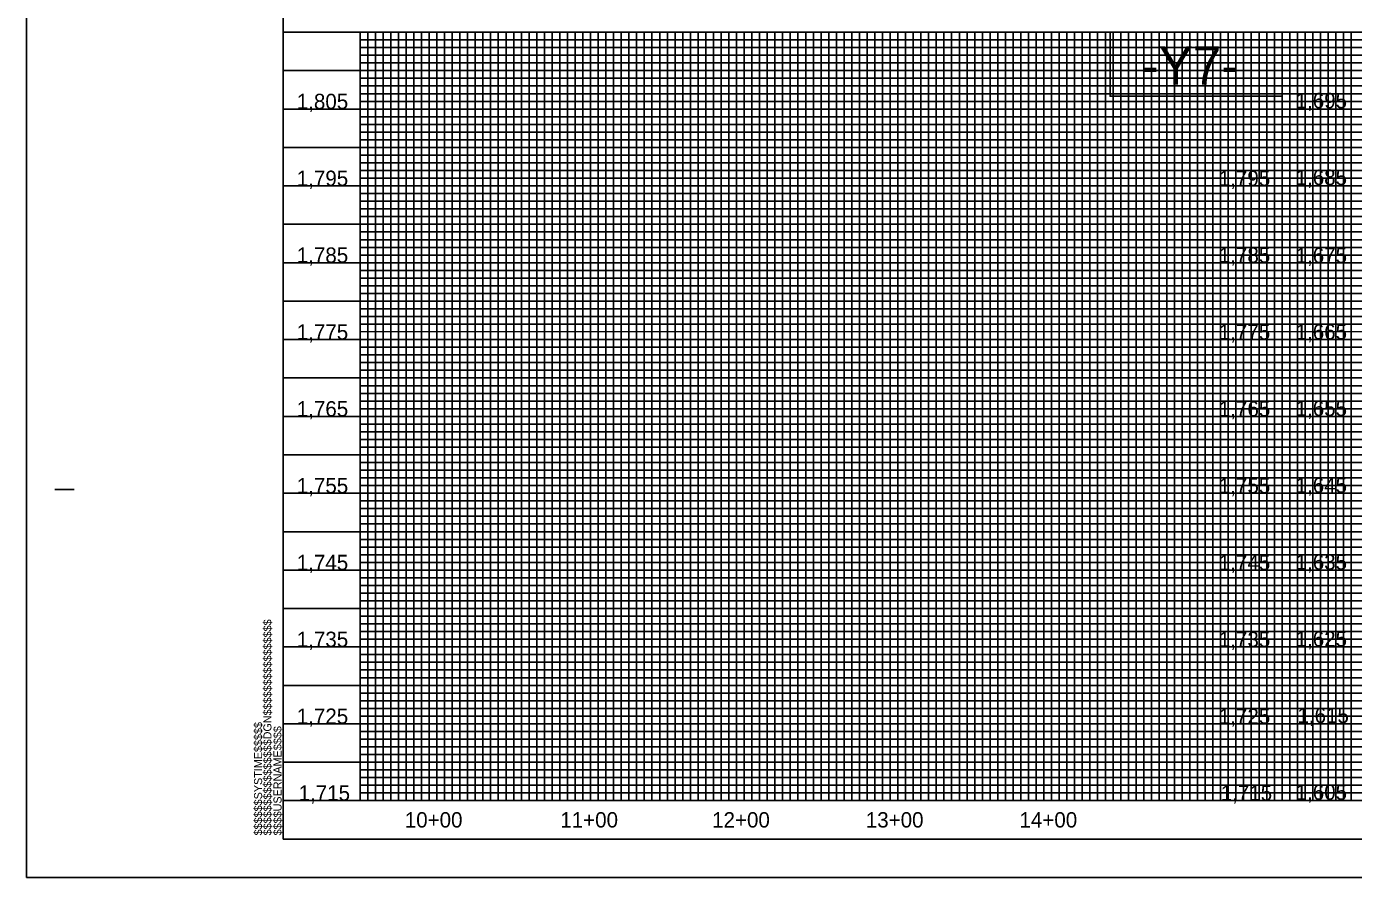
# Model space of a CAD drawing. Extents: x 505602 to 507286, y 483109 to 489436.
# Drawn here: x 505602 to 506466, y 483109 to 483662 of the extents above; entities that cross this region are included whole.
import ezdxf

# ---------------------------------------------------------------- set-up
doc = ezdxf.new("R2010")
doc.units = 0
for name, color, linetype in [('Exist Vertical Profile Vertical Axis Label', 7, 'Continuous'), ('Old_Level_1', 7, 'Continuous'), ('Prop Grid Mask', 7, 'Continuous'), ('Sheet Layout Profile Border Port 2', 7, 'Continuous'), ('Sheet Plot Border Outside CELL', 7, 'Continuous'), ('Sheet Profile CELL', 7, 'Continuous'), ('Sheet Profile Grid Major CELL', 7, 'Continuous'), ('Sheet Profile Grid Middle CELL', 7, 'Continuous'), ('Sheet Profile Grid Minor CELL', 7, 'Continuous')]:
    doc.layers.add(name, color=color, linetype=linetype)

msp = doc.modelspace()

# ---------------------------------------------------------------- linework, layer by layer
at = {"layer": 'Prop Grid Mask'}
msp.add_lwpolyline([(506419.08, 483658.71), (506307.17, 483658.71), (506307.17, 483617), (506419.08, 483617)], close=True, dxfattribs=at)
at = {"layer": 'Sheet Layout Profile Border Port 2'}
msp.add_lwpolyline([(505819.08, 483658.71), (506419.08, 483658.71), (506419.08, 483158.71), (505819.08, 483158.71)], close=True, dxfattribs=at)
at = {"layer": 'Sheet Plot Border Outside CELL'}
msp.add_lwpolyline([(505602.08, 483108.71), (507286.08, 483108.71), (507286.08, 484208.71), (505602.08, 484208.71)], close=True, dxfattribs=at)
at = {"layer": 'Sheet Profile CELL'}
for p, q in [((505769.08, 483658.71), (507269.08, 483658.71)), ((506419.08, 483158.71), (506419.08, 483658.71)), ((505620.58, 483361.21), (505633.08, 483361.21)), ((507269.08, 483158.71), (505769.08, 483158.71)), ((505769.08, 483133.71), (507269.08, 483133.71)), ((505769.08, 483133.71), (505769.08, 483133.71)), ((505769.08, 483133.71), (505769.08, 483133.71)), ((505769.08, 483133.71), (505769.08, 483133.71)), ((505769.08, 483133.71), (505769.08, 483133.71)), ((505769.08, 483133.71), (505769.08, 483133.71)), ((505769.08, 483133.71), (505769.08, 483133.71)), ((505769.08, 483133.71), (505769.08, 483133.71))]:
    msp.add_line(p, q, dxfattribs=at)
msp.add_lwpolyline([(507269.08, 484183.71), (505769.08, 484183.71), (505769.08, 483133.71), (507269.08, 483133.71)], close=True, dxfattribs=at)
msp.add_lwpolyline([(505806.58, 483133.71), (505806.58, 483133.71)], dxfattribs=at)
at = {"layer": 'Sheet Profile Grid Major CELL'}
for p, q in [((506269.08, 483658.71), (506319.08, 483658.71)), ((506369.08, 483658.71), (506419.08, 483658.71))]:
    msp.add_line(p, q, dxfattribs=at)
for points in [[(505819.08, 483658.71), (505819.08, 483158.71), (505869.08, 483158.71), (505869.08, 483658.71), (505919.08, 483658.71), (505919.08, 483158.71), (505969.08, 483158.71), (505969.08, 483658.71), (506019.08, 483658.71), (506019.08, 483158.71), (506069.08, 483158.71), (506069.08, 483658.71), (506119.08, 483658.71), (506119.08, 483158.71), (506169.08, 483158.71), (506169.08, 483658.71), (506219.08, 483658.71), (506219.08, 483158.71), (506269.08, 483158.71), (506269.08, 483658.71), (506319.08, 483658.71), (506319.08, 483158.71), (506369.08, 483158.71), (506369.08, 483658.71), (506419.08, 483658.71), (506419.08, 483158.71), (506469.08, 483158.71)], [(505819.08, 483658.71), (505819.08, 483158.71), (505869.08, 483158.71), (505869.08, 483658.71), (505919.08, 483658.71), (505919.08, 483158.71), (505969.08, 483158.71), (505969.08, 483658.71), (506019.08, 483658.71), (506019.08, 483158.71), (506069.08, 483158.71), (506069.08, 483658.71), (506119.08, 483658.71), (506119.08, 483158.71), (506169.08, 483158.71), (506169.08, 483658.71), (506219.08, 483658.71), (506219.08, 483158.71), (506269.08, 483158.71), (506269.08, 483658.71), (506319.08, 483658.71), (506319.08, 483158.71), (506369.08, 483158.71), (506369.08, 483658.71), (506419.08, 483658.71), (506419.08, 483158.71), (506469.08, 483158.71)], [(507269.08, 483608.71), (505769.08, 483608.71)], [(507269.08, 483558.71), (505769.08, 483558.71), (505769.08, 483508.71), (507269.08, 483508.71)], [(507269.08, 483458.71), (505769.08, 483458.71), (505769.08, 483408.71), (507269.08, 483408.71)], [(507269.08, 483358.71), (505769.08, 483358.71), (505769.08, 483308.71), (507269.08, 483308.71)], [(507269.08, 483258.71), (505769.08, 483258.71), (505769.08, 483258.71), (505769.08, 483208.71), (507269.08, 483208.71)], [(507269.08, 483158.71), (505769.08, 483158.71)]]:
    msp.add_lwpolyline(points, dxfattribs=at)
at = {"layer": 'Sheet Profile Grid Middle CELL'}
for points in [[(505794.08, 483658.71), (505844.08, 483658.71), (505844.08, 483158.71), (505894.08, 483158.71), (505894.08, 483658.71), (505944.08, 483658.71), (505944.08, 483158.71), (505994.08, 483158.71), (505994.08, 483658.71), (506044.08, 483658.71), (506044.08, 483158.71), (506094.08, 483158.71), (506094.08, 483658.71), (506144.08, 483658.71), (506144.08, 483158.71), (506194.08, 483158.71), (506194.08, 483658.71), (506244.08, 483658.71), (506244.08, 483158.71), (506294.08, 483158.71), (506294.08, 483658.71), (506344.08, 483658.71), (506344.08, 483158.71), (506394.08, 483158.71), (506394.08, 483158.71), (506394.08, 483658.71), (506444.08, 483658.71), (506444.08, 483158.71), (506494.08, 483158.71)], [(505769.08, 483633.71), (507269.08, 483633.71)], [(507269.08, 483583.71), (505769.08, 483583.71), (505769.08, 483533.71), (507269.08, 483533.71)], [(507269.08, 483483.71), (505769.08, 483483.71), (505769.08, 483433.71), (507269.08, 483433.71)], [(507269.08, 483383.71), (505769.08, 483383.71), (505769.08, 483333.71), (507269.08, 483333.71)], [(507269.08, 483283.71), (505769.08, 483283.71), (505769.08, 483233.71), (507269.08, 483233.71)], [(507269.08, 483183.71), (505769.08, 483183.71)]]:
    msp.add_lwpolyline(points, dxfattribs=at)
at = {"layer": 'Sheet Profile Grid Minor CELL'}
for p, q in [((505819.08, 483653.71), (507219.08, 483653.71)), ((507219.08, 483648.71), (505819.08, 483648.71)), ((505819.08, 483643.71), (507219.08, 483643.71)), ((507219.08, 483638.71), (505819.08, 483638.71)), ((505819.08, 483628.71), (507219.08, 483628.71)), ((507219.08, 483623.71), (505819.08, 483623.71)), ((505819.08, 483618.71), (507219.08, 483618.71)), ((507219.08, 483613.71), (505819.08, 483613.71)), ((505819.08, 483603.71), (507219.08, 483603.71)), ((507219.08, 483598.71), (505819.08, 483598.71)), ((505819.08, 483593.71), (507219.08, 483593.71)), ((507219.08, 483588.71), (505819.08, 483588.71)), ((505819.08, 483578.71), (507219.08, 483578.71)), ((507219.08, 483573.71), (505819.08, 483573.71)), ((505819.08, 483568.71), (507219.08, 483568.71)), ((507219.08, 483563.71), (505819.08, 483563.71)), ((505819.08, 483553.71), (507219.08, 483553.71)), ((507219.08, 483548.71), (505819.08, 483548.71)), ((505819.08, 483543.71), (507219.08, 483543.71)), ((507219.08, 483538.71), (505819.08, 483538.71)), ((505819.08, 483528.71), (507219.08, 483528.71)), ((507219.08, 483523.71), (505819.08, 483523.71)), ((505819.08, 483518.71), (507219.08, 483518.71)), ((507219.08, 483513.71), (505819.08, 483513.71)), ((505819.08, 483503.71), (507219.08, 483503.71)), ((507219.08, 483498.71), (505819.08, 483498.71)), ((505819.08, 483493.71), (507219.08, 483493.71)), ((507219.08, 483488.71), (505819.08, 483488.71)), ((505819.08, 483478.71), (507219.08, 483478.71)), ((507219.08, 483473.71), (505819.08, 483473.71)), ((505819.08, 483468.71), (507219.08, 483468.71)), ((507219.08, 483463.71), (505819.08, 483463.86)), ((505819.08, 483453.71), (507219.08, 483453.71)), ((507219.08, 483448.71), (505819.08, 483448.71)), ((505819.08, 483443.71), (507219.08, 483443.71)), ((507219.08, 483438.71), (505819.08, 483438.71)), ((505819.08, 483428.71), (507219.08, 483428.71)), ((507219.08, 483423.71), (505819.08, 483423.71)), ((505819.08, 483418.71), (507219.08, 483418.71)), ((507219.08, 483413.71), (505819.08, 483413.71)), ((505819.08, 483403.71), (507219.08, 483403.71)), ((507219.08, 483398.71), (505819.08, 483398.71)), ((505819.08, 483393.71), (507219.08, 483393.71)), ((507219.08, 483388.71), (505819.08, 483388.71)), ((505819.08, 483378.71), (507219.08, 483378.71)), ((507219.08, 483373.71), (505819.08, 483373.71)), ((505819.08, 483368.71), (507219.08, 483368.71)), ((507219.08, 483363.71), (505819.08, 483363.71)), ((505819.08, 483353.71), (507219.08, 483353.71)), ((507219.08, 483348.71), (505819.08, 483348.71)), ((505819.08, 483343.71), (507219.08, 483343.71)), ((507219.08, 483338.71), (505819.08, 483338.71)), ((505819.08, 483328.71), (507219.08, 483328.71)), ((507219.08, 483323.71), (505819.08, 483323.71)), ((505819.08, 483318.71), (507219.08, 483318.71)), ((507219.08, 483313.71), (505819.08, 483313.71)), ((505819.08, 483303.71), (507219.08, 483303.71)), ((507219.08, 483298.71), (505819.08, 483298.71)), ((505819.08, 483293.71), (507219.08, 483293.71)), ((507219.08, 483288.71), (505819.08, 483288.71)), ((505819.08, 483278.71), (507219.08, 483278.71)), ((507219.08, 483273.71), (505819.08, 483273.71)), ((505819.08, 483268.71), (507219.08, 483268.71)), ((507219.08, 483263.71), (505819.08, 483263.71)), ((505819.08, 483253.71), (507219.08, 483253.71)), ((507219.08, 483248.71), (505819.08, 483248.71)), ((505819.08, 483243.71), (507219.08, 483243.71)), ((507219.08, 483238.71), (505819.08, 483238.71)), ((505819.08, 483228.71), (507219.08, 483228.71)), ((507219.08, 483223.71), (505819.08, 483223.71)), ((505819.08, 483218.71), (507219.08, 483218.71)), ((507219.08, 483213.71), (505819.08, 483213.71)), ((505819.08, 483203.71), (507219.08, 483203.71)), ((507219.08, 483198.71), (505819.08, 483198.71)), ((505819.08, 483193.71), (507219.08, 483193.71)), ((507219.08, 483188.71), (505819.08, 483188.71)), ((505819.08, 483178.71), (507219.08, 483178.71)), ((507219.08, 483173.71), (505819.08, 483173.71)), ((505819.08, 483168.71), (507219.08, 483168.71)), ((505819.08, 483163.71), (507219.08, 483163.71))]:
    msp.add_line(p, q, dxfattribs=at)
for points in [[(505819.08, 483658.71), (505824.08, 483658.71), (505824.08, 483158.71), (505829.08, 483158.71), (505829.08, 483658.71), (505834.08, 483658.71), (505834.08, 483158.71), (505839.08, 483158.71), (505839.08, 483658.71), (505849.08, 483658.71), (505849.08, 483158.71), (505854.08, 483158.71), (505854.08, 483658.71), (505859.08, 483658.71), (505859.08, 483158.71), (505864.08, 483158.71), (505874.08, 483158.71), (505879.08, 483158.71), (505879.08, 483658.71), (505884.08, 483658.71), (505884.08, 483158.71), (505889.08, 483158.71), (505889.08, 483658.71), (505899.08, 483658.71), (505899.08, 483158.71), (505904.08, 483158.71), (505904.08, 483658.71), (505909.08, 483658.71), (505909.08, 483158.71), (505914.08, 483158.71), (505914.08, 483658.71), (505924.08, 483658.71), (505924.08, 483158.71), (505929.08, 483158.71), (505929.08, 483658.71), (505934.08, 483658.71), (505934.08, 483158.71), (505939.08, 483158.71), (505939.08, 483658.71), (505949.08, 483658.71), (505949.08, 483158.71), (505954.08, 483158.71), (505954.08, 483658.71), (505959.08, 483658.71), (505959.08, 483158.71), (505964.08, 483158.71), (505964.08, 483658.71), (505974.08, 483658.71), (505974.08, 483158.71), (505979.08, 483158.71), (505979.08, 483658.71), (505984.08, 483658.71), (505984.08, 483158.71), (505989.08, 483158.71), (505989.08, 483658.71), (505999.08, 483658.71), (505999.08, 483158.71), (506004.08, 483158.71), (506004.08, 483658.71), (506009.08, 483658.71), (506009.08, 483158.71), (506014.08, 483158.71), (506014.08, 483658.71), (506024.08, 483658.71), (506024.08, 483158.71), (506029.08, 483158.71), (506029.08, 483658.71), (506034.08, 483658.71), (506034.08, 483158.71)], [(505864.08, 483158.71), (505864.08, 483658.71), (505874.08, 483658.71), (505874.08, 483158.71)], [(506034.08, 483158.71), (506039.08, 483158.71), (506039.08, 483658.71), (506049.08, 483658.71), (506049.08, 483158.71), (506054.08, 483158.71), (506054.08, 483658.71), (506059.08, 483658.71), (506059.08, 483158.71), (506064.08, 483158.71), (506064.08, 483658.71), (506074.08, 483658.71), (506074.08, 483158.71), (506079.08, 483158.71), (506079.08, 483658.71), (506084.08, 483658.71), (506084.08, 483158.71), (506089.08, 483158.71), (506089.08, 483658.71), (506099.08, 483658.71), (506099.08, 483158.71), (506104.08, 483158.71), (506104.08, 483658.71), (506109.08, 483658.71), (506109.08, 483158.71), (506114.08, 483158.71), (506114.08, 483658.71), (506124.08, 483658.71), (506124.08, 483158.71), (506129.08, 483158.71), (506129.08, 483658.71), (506134.08, 483658.71), (506134.08, 483158.71), (506139.08, 483158.71), (506139.08, 483658.71), (506149.08, 483658.71), (506149.08, 483158.71), (506154.08, 483158.71), (506154.08, 483658.71), (506159.08, 483658.71), (506159.08, 483158.71), (506164.08, 483158.71), (506164.08, 483658.71), (506174.08, 483658.71), (506174.08, 483158.71), (506179.08, 483158.71), (506179.08, 483658.71), (506184.08, 483658.71), (506184.08, 483158.71), (506189.08, 483158.71), (506189.08, 483658.71), (506199.08, 483658.71), (506199.08, 483158.71), (506204.08, 483158.71), (506204.08, 483658.71), (506209.08, 483658.71), (506209.08, 483158.71), (506214.08, 483158.71), (506214.08, 483658.71), (506224.08, 483658.71), (506224.08, 483158.71), (506229.08, 483158.71), (506229.08, 483658.71), (506234.08, 483658.71), (506234.08, 483158.71), (506239.08, 483158.71), (506239.08, 483658.71), (506249.08, 483658.71), (506249.08, 483158.71), (506254.08, 483158.71), (506254.08, 483658.71), (506259.08, 483658.71), (506259.08, 483158.71), (506264.08, 483158.71), (506264.08, 483658.71), (506274.08, 483658.71), (506274.08, 483158.71), (506279.08, 483158.71), (506279.08, 483658.71), (506284.08, 483658.71), (506284.08, 483158.71), (506289.08, 483158.71), (506289.08, 483658.71), (506299.08, 483658.71), (506299.08, 483158.71), (506304.08, 483158.71), (506304.08, 483658.71), (506309.08, 483658.71), (506309.08, 483158.71), (506314.08, 483158.71), (506314.08, 483658.71), (506324.08, 483658.71), (506324.08, 483158.71), (506329.08, 483158.71), (506329.08, 483658.71), (506334.08, 483658.71), (506334.08, 483158.71), (506339.08, 483158.71), (506339.08, 483658.71), (506349.08, 483658.71)], [(506349.08, 483658.71), (506349.08, 483158.71), (506354.08, 483158.71), (506354.08, 483658.71), (506359.08, 483658.71), (506359.08, 483158.71), (506364.08, 483158.71), (506364.08, 483658.71), (506374.08, 483658.71), (506374.08, 483158.71), (506379.08, 483158.71), (506379.08, 483658.71), (506384.08, 483658.71), (506384.08, 483158.71), (506389.08, 483158.71), (506389.08, 483658.71), (506399.08, 483658.71), (506399.08, 483158.71), (506404.08, 483158.71), (506404.08, 483658.71), (506409.08, 483658.71), (506409.08, 483158.71), (506414.08, 483158.71), (506414.08, 483658.71), (506424.08, 483658.71), (506424.08, 483158.71), (506429.08, 483158.71), (506429.08, 483658.71), (506434.08, 483658.71), (506434.08, 483158.71), (506439.08, 483158.71), (506439.08, 483658.71), (506449.08, 483658.71), (506449.08, 483158.71), (506454.08, 483158.71), (506454.08, 483658.71), (506459.08, 483658.71), (506459.08, 483158.71), (506464.08, 483158.71), (506464.08, 483658.71), (506474.08, 483658.71)]]:
    msp.add_lwpolyline(points, dxfattribs=at)

# ---------------------------------------------------------------- texts
at = {"layer": 'Exist Vertical Profile Vertical Axis Label'}
for s, p in [('1,805', (505777.93, 483608.64)), ('1,695', (506427.9, 483609.19)), ('1,795', (505777.93, 483558.64)), ('1,795', (506377.93, 483558.64)), ('1,685', (506427.9, 483559.26)), ('1,785', (505777.93, 483508.64)), ('1,785', (506377.93, 483508.64)), ('1,675', (506427.9, 483508.48)), ('1,775', (505777.93, 483458.64)), ('1,775', (506377.93, 483458.64)), ('1,665', (506427.9, 483458.72)), ('1,765', (505777.93, 483408.64)), ('1,765', (506377.93, 483408.64)), ('1,655', (506427.9, 483408.96)), ('1,755', (505777.93, 483358.64)), ('1,755', (506377.93, 483358.64)), ('1,645', (506427.9, 483358.96)), ('1,745', (505777.93, 483308.64)), ('1,745', (506377.93, 483308.64)), ('1,635', (506427.9, 483308.96)), ('1,735', (505777.93, 483258.64)), ('1,735', (506377.93, 483258.64)), ('1,625', (506427.9, 483258.96)), ('1,615', (506429.1, 483209.2)), ('1,725', (505777.93, 483208.64)), ('1,725', (506377.93, 483208.64)), ('1,715', (505779.13, 483158.64)), ('1,715', (506379.13, 483158.64)), ('1,605', (506427.9, 483159.2)), ('10+00', (505848.21, 483141.21)), ('11+00', (505949.41, 483141.21)), ('12+00', (506048.21, 483141.21)), ('13+00', (506148.21, 483141.21)), ('14+00', (506248.21, 483141.21))]:
    msp.add_text(s, height=10, dxfattribs=at).set_placement(p)
at = {"layer": 'Old_Level_1'}
msp.add_text('-Y7-', height=25, dxfattribs=at).set_placement((506327.55, 483624.54))
at = {"layer": 'Sheet Profile CELL'}
for s, p in [('$$$$$$$$$$$$$$$$DGN$$$$$$$$$$$$$$$$', (505761.44, 483136.09)), ('$$$$$$SYSTIME$$$$$', (505755.39, 483136.09)), ('$$$$USERNAME$$$$', (505768.02, 483136.1))]:
    msp.add_text(s, height=5.25, rotation=90, dxfattribs=at).set_placement(p)

doc.saveas('drawing.dxf')
